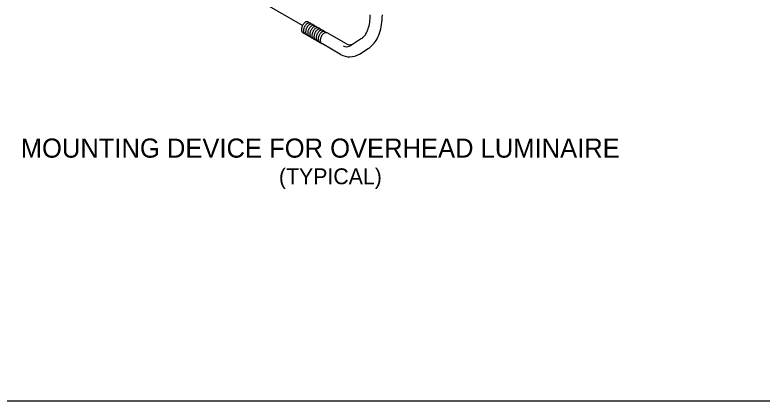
# Model space of a CAD drawing. Extents: x 99968 to 128667, y 90163 to 102182.
# Drawn here: x 117408 to 118112, y 96677 to 97041 of the extents above; entities that cross this region are included whole.
import ezdxf

# ---------------------------------------------------------------- set-up
doc = ezdxf.new("R2010")
doc.units = 0
doc.layers.add('Default', color=7, linetype='Continuous')
doc.layers.add('RD Standard Plans Active', color=7, linetype='Continuous')

msp = doc.modelspace()

# ---------------------------------------------------------------- linework, layer by layer
at = {"layer": 'Default'}
msp.add_lwpolyline([(115267.47, 98876.5), (118467.15, 98876.5), (118467.15, 96676.9), (115267.47, 96676.9)], close=True, dxfattribs=at)
at = {"layer": 'RD Standard Plans Active'}
for p, q in [((117679.07, 97030.83), (117575.57, 97090.58)), ((117684.4, 97034.33), (117685.07, 97033.58)), ((117686.37, 97033.2), (117687.05, 97032.43)), ((117688.35, 97032.05), (117689, 97031.3)), ((117690.32, 97030.93), (117691, 97030.15)), ((117692.3, 97029.78), (117693, 97029)), ((117694.27, 97028.63), (117694.92, 97027.88)), ((117696.22, 97027.5), (117696.92, 97026.73)), ((117698.2, 97026.35), (117698.87, 97025.6)), ((117700.17, 97025.23), (117700.87, 97024.45)), ((117679.92, 97023.73), (117680.77, 97023.58)), ((117681.9, 97022.6), (117682.75, 97022.45)), ((117683.87, 97021.45), (117684.72, 97021.3)), ((117685.85, 97020.33), (117686.7, 97020.15)), ((117687.82, 97019.18), (117688.67, 97019.03)), ((117689.8, 97018.03), (117690.62, 97017.9)), ((117720.42, 97013.55), (117702.15, 97024.08)), ((117726.03, 97013.37), (117734.67, 97018.8)), ((117691.75, 97016.9), (117692.57, 97016.75)), ((117693.72, 97015.75), (117694.57, 97015.6)), ((117695.7, 97014.63), (117696.55, 97014.48)), ((117714.7, 97003.68), (117697.67, 97013.5)), ((117723.49, 97011.77), (117726.03, 97013.37)), ((117732.57, 97004), (117740.75, 97009.13))]:
    msp.add_line(p, q, dxfattribs=at)
for centre, radius, end in [((117720.35, 97016.81), 5.94, 302.06726), ((117723.37, 97018.68), 5.94, 296.62266), ((117723.37, 97018.68), 17.34, 302.06726)]:
    msp.add_arc(centre, radius, 239.95348, end, dxfattribs=at)
for points in [[(117734.7, 97018.78), (117735.15, 97019.05), (117736.55, 97020.08), (117738.75, 97022.68), (117740.97, 97027.35), (117742.47, 97033.63), (117742.85, 97038.15), (117742.8, 97040.83)], [(117740.75, 97009.08), (117741.5, 97009.55), (117744.4, 97011.63), (117748.4, 97016.43), (117751.77, 97023.45), (117753.77, 97031.78), (117754.25, 97037.75), (117754.2, 97040.98)], [(117678.25, 97027.08), (117678.27, 97027.45), (117678.3, 97028.2), (117678.52, 97029.25), (117678.85, 97030.33), (117679.3, 97031.33), (117679.85, 97032.28), (117680.45, 97033.1), (117681.12, 97033.78), (117681.62, 97034.15), (117681.87, 97034.3)], [(117680.22, 97025.95), (117680.25, 97026.33), (117680.27, 97027.08), (117680.5, 97028.13), (117680.82, 97029.2), (117681.27, 97030.2), (117681.82, 97031.15), (117682.42, 97031.98), (117683.1, 97032.65), (117683.6, 97033.03), (117683.85, 97033.18)], [(117681.87, 97034.3), (117682.1, 97034.45), (117682.55, 97034.63), (117683.25, 97034.75), (117683.87, 97034.63), (117684.25, 97034.43), (117684.4, 97034.33)], [(117682.2, 97024.8), (117682.22, 97025.18), (117682.25, 97025.93), (117682.47, 97026.98), (117682.8, 97028.05), (117683.25, 97029.05), (117683.8, 97030), (117684.4, 97030.83), (117685.07, 97031.5), (117685.57, 97031.88), (117685.82, 97032.03)], [(117683.85, 97033.18), (117684.07, 97033.33), (117684.52, 97033.5), (117685.22, 97033.63), (117685.85, 97033.5), (117686.22, 97033.3), (117686.37, 97033.2)], [(117685.82, 97032.03), (117686.05, 97032.18), (117686.5, 97032.35), (117687.2, 97032.48), (117687.82, 97032.35), (117688.2, 97032.15), (117688.35, 97032.05)], [(117679.92, 97023.73), (117679.9, 97023.75), (117679.67, 97023.83), (117679.27, 97024.05), (117678.85, 97024.58), (117678.52, 97025.25), (117678.3, 97026.13), (117678.25, 97026.73), (117678.25, 97027.08)], [(117681.9, 97022.6), (117681.87, 97022.63), (117681.65, 97022.7), (117681.25, 97022.93), (117680.82, 97023.45), (117680.5, 97024.13), (117680.27, 97025), (117680.22, 97025.6), (117680.22, 97025.95)], [(117683.87, 97021.45), (117683.85, 97021.48), (117683.62, 97021.55), (117683.22, 97021.78), (117682.8, 97022.3), (117682.47, 97022.98), (117682.25, 97023.85), (117682.2, 97024.45), (117682.2, 97024.8)], [(117684.17, 97023.68), (117684.2, 97024.05), (117684.22, 97024.8), (117684.45, 97025.85), (117684.77, 97026.93), (117685.22, 97027.93), (117685.77, 97028.88), (117686.37, 97029.7), (117687.05, 97030.38), (117687.55, 97030.75), (117687.8, 97030.9)], [(117686.15, 97022.53), (117686.17, 97022.9), (117686.2, 97023.65), (117686.42, 97024.7), (117686.75, 97025.78), (117687.2, 97026.78), (117687.75, 97027.73), (117688.35, 97028.55), (117689.02, 97029.23), (117689.52, 97029.6), (117689.77, 97029.75)], [(117687.8, 97030.9), (117688.02, 97031.05), (117688.47, 97031.23), (117689.17, 97031.35), (117689.8, 97031.23), (117690.17, 97031.03), (117690.32, 97030.93)], [(117688.12, 97021.38), (117688.15, 97021.75), (117688.17, 97022.5), (117688.4, 97023.55), (117688.72, 97024.63), (117689.17, 97025.63), (117689.72, 97026.58), (117690.32, 97027.4), (117691, 97028.08), (117691.5, 97028.45), (117691.75, 97028.6)], [(117689.77, 97029.75), (117690, 97029.9), (117690.45, 97030.08), (117691.15, 97030.2), (117691.77, 97030.08), (117692.15, 97029.88), (117692.3, 97029.78)], [(117690.07, 97020.25), (117690.1, 97020.63), (117690.12, 97021.38), (117690.35, 97022.43), (117690.67, 97023.5), (117691.12, 97024.5), (117691.67, 97025.45), (117692.27, 97026.28), (117692.95, 97026.95), (117693.45, 97027.33), (117693.7, 97027.48)], [(117691.75, 97028.6), (117691.97, 97028.75), (117692.42, 97028.93), (117693.12, 97029.05), (117693.75, 97028.93), (117694.12, 97028.73), (117694.27, 97028.63)], [(117692.05, 97019.1), (117692.07, 97019.48), (117692.1, 97020.23), (117692.32, 97021.28), (117692.65, 97022.35), (117693.1, 97023.35), (117693.65, 97024.3), (117694.25, 97025.13), (117694.92, 97025.8), (117695.42, 97026.18), (117695.67, 97026.33)], [(117693.7, 97027.48), (117693.92, 97027.63), (117694.37, 97027.8), (117695.07, 97027.93), (117695.7, 97027.8), (117696.07, 97027.6), (117696.22, 97027.5)], [(117694.02, 97017.98), (117694.05, 97018.35), (117694.07, 97019.1), (117694.3, 97020.15), (117694.62, 97021.23), (117695.07, 97022.23), (117695.62, 97023.18), (117696.22, 97024), (117696.9, 97024.68), (117697.4, 97025.05), (117697.65, 97025.2)], [(117695.67, 97026.33), (117695.9, 97026.48), (117696.35, 97026.65), (117697.05, 97026.78), (117697.67, 97026.65), (117698.05, 97026.45), (117698.2, 97026.35)], [(117697.65, 97025.2), (117697.87, 97025.35), (117698.32, 97025.53), (117699.02, 97025.65), (117699.65, 97025.53), (117700.02, 97025.33), (117700.17, 97025.23)], [(117685.85, 97020.33), (117685.82, 97020.35), (117685.6, 97020.43), (117685.2, 97020.65), (117684.77, 97021.18), (117684.45, 97021.85), (117684.22, 97022.73), (117684.17, 97023.33), (117684.17, 97023.68)], [(117687.82, 97019.18), (117687.8, 97019.2), (117687.57, 97019.28), (117687.17, 97019.5), (117686.75, 97020.03), (117686.42, 97020.7), (117686.2, 97021.58), (117686.15, 97022.18), (117686.15, 97022.53)], [(117689.8, 97018.03), (117689.77, 97018.05), (117689.55, 97018.13), (117689.15, 97018.35), (117688.72, 97018.88), (117688.4, 97019.55), (117688.17, 97020.43), (117688.12, 97021.03), (117688.12, 97021.38)], [(117691.75, 97016.9), (117691.72, 97016.93), (117691.5, 97017), (117691.1, 97017.23), (117690.67, 97017.75), (117690.35, 97018.43), (117690.12, 97019.3), (117690.07, 97019.9), (117690.07, 97020.25)], [(117693.72, 97015.75), (117693.7, 97015.78), (117693.47, 97015.85), (117693.07, 97016.08), (117692.65, 97016.6), (117692.32, 97017.28), (117692.1, 97018.15), (117692.05, 97018.75), (117692.05, 97019.1)], [(117695.7, 97014.63), (117695.67, 97014.65), (117695.45, 97014.73), (117695.05, 97014.95), (117694.62, 97015.48), (117694.3, 97016.15), (117694.07, 97017.03), (117694.02, 97017.63), (117694.02, 97017.98)], [(117696, 97016.83), (117696.02, 97017.2), (117696.05, 97017.95), (117696.27, 97019), (117696.6, 97020.08), (117697.05, 97021.08), (117697.6, 97022.03), (117698.2, 97022.85), (117698.87, 97023.53), (117699.37, 97023.9), (117699.62, 97024.05)], [(117699.62, 97024.05), (117699.85, 97024.2), (117700.3, 97024.38), (117701, 97024.5), (117701.62, 97024.38), (117702, 97024.18), (117702.15, 97024.08)], [(117697.67, 97013.48), (117697.65, 97013.5), (117697.42, 97013.58), (117697.02, 97013.8), (117696.6, 97014.33), (117696.27, 97015), (117696.05, 97015.88), (117696, 97016.48), (117696, 97016.83)]]:
    msp.add_open_spline(points, degree=3, dxfattribs=at)

# ---------------------------------------------------------------- texts
for s, height, p in [('MOUNTING DEVICE FOR OVERHEAD LUMINAIRE', 18, (117413.51, 96906.34)), ('(TYPICAL)', 15, (117656.78, 96881.24))]:
    msp.add_text(s, height=height, dxfattribs=at).set_placement(p)

doc.saveas('drawing.dxf')
